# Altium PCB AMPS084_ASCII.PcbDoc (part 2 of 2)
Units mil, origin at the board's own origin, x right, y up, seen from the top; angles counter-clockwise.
Board outline 7000 x 5000 mil, 4 copper layers (Top Layer, Int 2 V-, Int 3 V+, Bottom Layer), stack 61.634 mil thick; 175 components, 69 nets, 389 pads, 136 vias.
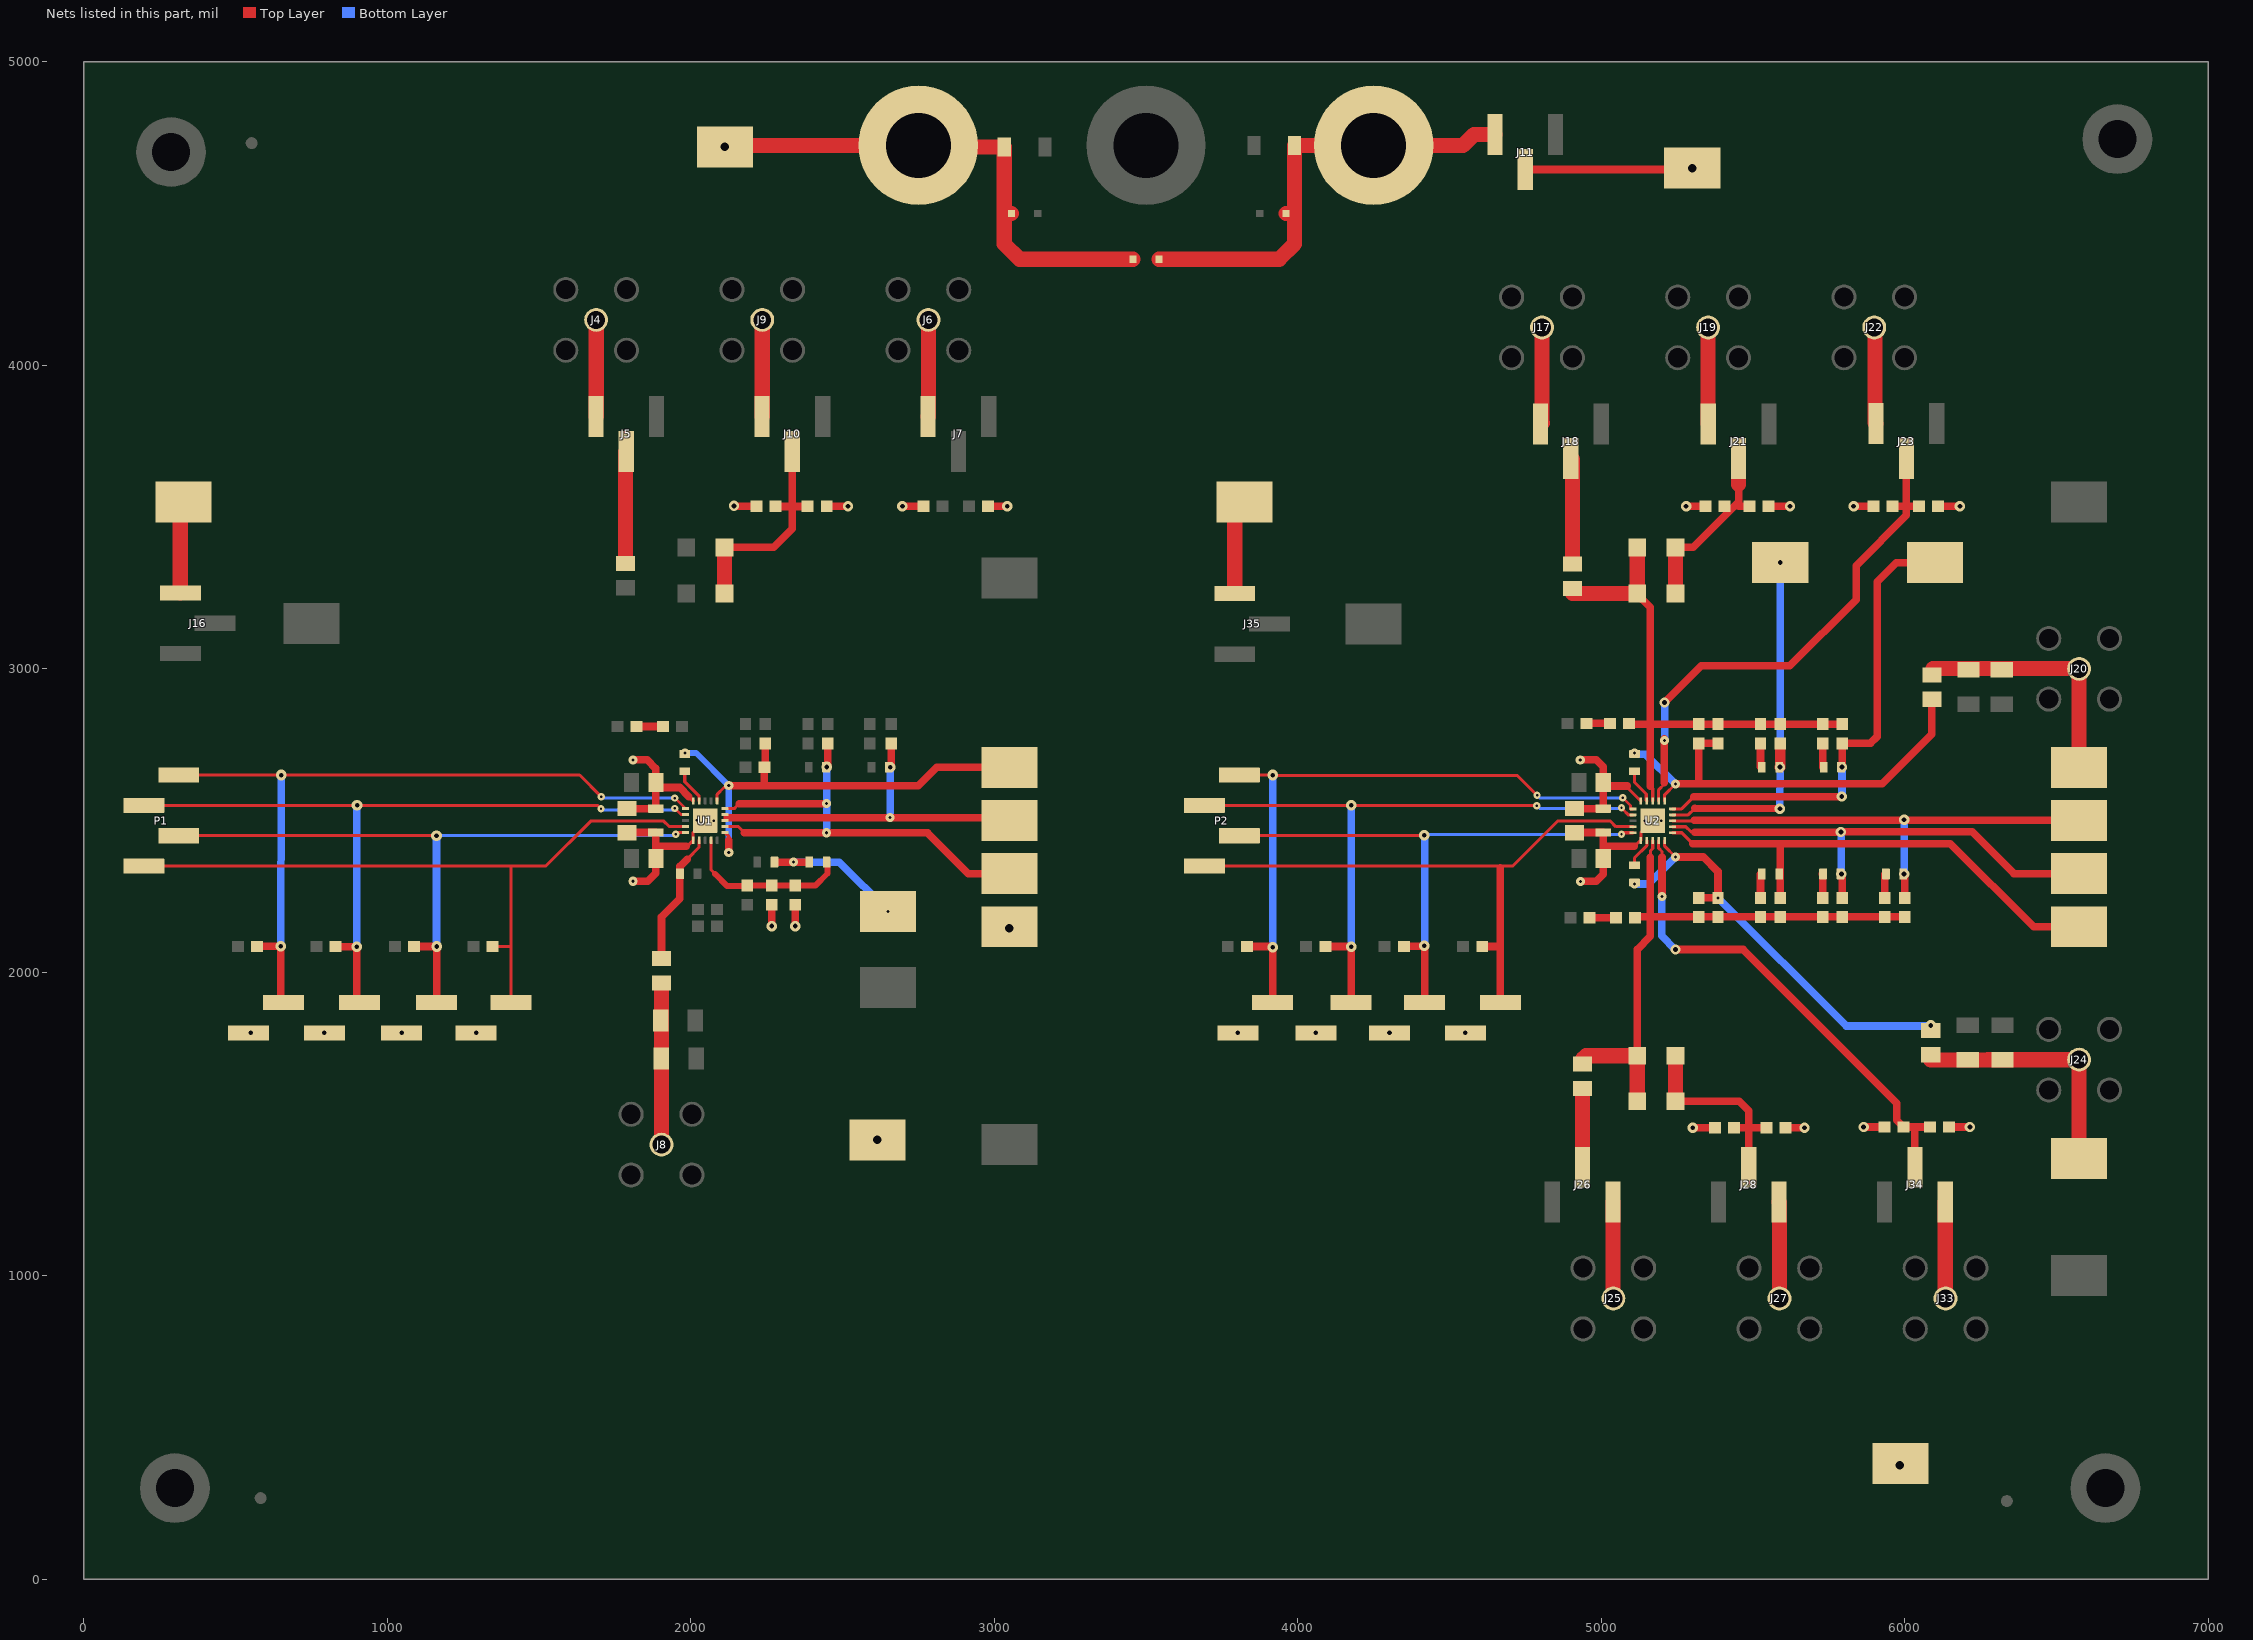
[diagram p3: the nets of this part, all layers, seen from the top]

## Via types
v1: diameter 34, hole 16, Top Layer to Bottom Layer, 61 vias
v2: diameter 35, hole 15, Top Layer to Bottom Layer, 28 vias
v3: diameter 30, hole 10, Top Layer to Bottom Layer, 22 vias
v4: diameter 24, hole 8, Top Layer to Bottom Layer, 16 vias
v5: diameter 50, hole 28, Top Layer to Bottom Layer, 9 vias

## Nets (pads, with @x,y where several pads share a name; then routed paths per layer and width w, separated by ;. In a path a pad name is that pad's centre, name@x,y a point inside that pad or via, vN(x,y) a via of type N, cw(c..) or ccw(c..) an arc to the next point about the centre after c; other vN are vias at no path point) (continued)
NetC6_1: C6.1 R5.1 | length 87
  Top Layer w25: C6.1@1821.5,2810 R5.1@1908.5,2810
NetC8_2: C8.2 J8.1 R11.2 R12.2 | length 515.9
  Top Layer w50: J8.1@1903.41,1432 R11.2@1903.41,1947.91
NetC12_1: C12.1 R28.1 | length 78.7
  Top Layer w25: C12.1@5730,2754.5 5730,2676.5 R28.1@5730.5,2676
NetC12_2: C12.2 C13.2 C15.2 D6.1 D7.2 R29.2 R30.1 R32.2 R33.1 R37.1 U2.18 | length 1774.3
  Top Layer w10: 5161.14,2613.79 5170,2604.93 U2.18@5170,2564.17
  Top Layer w25: R32.2@5091.5,2820 5093.5,2818 5161.14,2818 ; D6.1@5116.33,3247.96 5161.14,3203.15 5161.14,2818 ; 5161.14,2613.79 5161.14,2818 ; R30.1@5795,2817.5 R33.1@5590,2817.5 R37.1@5385,2817.5 5161.65,2817.5 5161.14,2818
  Top Layer w50: R29.2@4905.79,3247.96 5116.33,3247.96 5119.01,3250.64 D7.2@5119.01,3400
NetC13_1: C13.1 R31.1 | length 79.1
  Top Layer w25: C13.1@5525,2754.5 5525,2677.5 R31.1@5526.5,2676
NetC14_1: C14.1 R32.1 | length 77
  Top Layer w25: C14.1@4951.5,2820 R32.1@5028.5,2820
NetC16_2: C16.2 J20.1 R36.2 R38.2 TP19.1 | length 809.8
  Top Layer w50: R36.2@6093,3000.09 6093.91,3001 6576,3001 J20.1@6575,3000 TP19.1@6575,2675
NetC18_2: C18.2 J24.1 R42.2 R43.2 TP20.1 | length 811.4
  Top Layer w50: R42.2@6086,1710.98 R43.2@6208.03,1710.98 6273.34,1710.98 6274.36,1712 J24.1@6572,1712 ; TP20.1@6575,1387 J24.1@6575,1712
NetC22_2: C22.2 C24.2 C25.2 C26.2 D8.1 D9.2 R45.2 R48.2 R49.1 R52.1 R59.1 R61.1 U2.8 | length 1954.2
  Top Layer w10: 5161.91,2379.25 5162.1,2379.44 5162.1,2399.81 5170,2407.71 U2.8@5170,2434.25
  Top Layer w25: R48.2@5111.5,2180 5114,2182.5 5161.91,2182.5 ; D8.1@5118.73,1725 5118.73,2075 5161.91,2118.18 5161.91,2182.5 ; 5161.91,2379.25 5161.91,2182.5 ; R61.1@6000,2182.5 C25.2@5730,2182.5 C24.2@5525,2182.5 C22.2@5322,2182.5 5161.91,2182.5
  Top Layer w50: R45.2@4938.96,1714.28 4949.67,1725 D8.1@5118.73,1725 ; D9.2@5119.01,1575 D8.1@5119.01,1725
NetC23_1: C23.1 R48.1 | length 87
  Top Layer w25: C23.1@4961.5,2180 R48.1@5048.5,2180
NetC24_1: C24.1 R51.1 | length 79.1
  Top Layer w25: C24.1@5525,2245.5 5525,2322.5 R51.1@5526.5,2324
NetC25_1: C25.1 R58.1 | length 79.1
  Top Layer w25: R58.1@5728.5,2324 5730,2322.5 C25.1@5730,2245.5
NetC26_1: C26.1 R60.1 | length 78.7
  Top Layer w25: C26.1@5935,2245.5 5935,2323.5 R60.1@5935.5,2324
NetD4_2: D4.2 D5.1 J10.2 R15.1 R18.2 | length 762.9
  Top Layer w25: D5.1@2110.99,3400 2273,3400 2334.5,3461.5 2334.5,3535 ; R18.2@2278.99,3536 2279.99,3535 2334.5,3535 ; J10.2@2334.5,3716.5 2334.5,3535 ; R15.1@2385,3536 2384,3535 2334.5,3535
  Top Layer w50: D4.2@2110.79,3248.03 2110.99,3248.24 D5.1@2110.99,3400
NetD6_2: D6.2 D7.1 J21.2 R35.1 R39.2 | length 614.1
  Top Layer w25: D7.1@5244.99,3400 5302.93,3400 5452.93,3550 ; 5452.93,3607.94 5452.93,3550 ; R35.1@5488.5,3536 5452.93,3536 5452.93,3550
  Top Layer w50: D6.2@5244.99,3248 D7.1@5244.99,3400 ; 5452.93,3607.94 J21.2@5452.93,3692.5
NetD8_2: D8.2 D9.1 J28.2 R46.1 R47.2 | length 703.9
  Top Layer w25: D9.1@5244.99,1575 5455.11,1575 5486.46,1543.65 5486.46,1480.14 ; R46.1@5437.99,1487.74 5478.85,1487.74 5486.46,1480.14 ; J28.2@5486.46,1357.5 5486.46,1480.14 ; R47.2@5544.96,1487.74 5494.06,1487.74 5486.46,1480.14
  Top Layer w50: D9.1@5244.99,1575 D8.2@5244.99,1725
NetJ4_1: J4.1 J5.1 | length 317.8
  Top Layer w50: J5.1@1687.28,3831.56 1688.07,3832.34 J4.1@1688.07,4149.06
NetJ5_2: J5.2 R8.1 | length 353.3
  Top Layer w50: R8.1@1785.08,3364.17 1785.08,3714.35 J5.2@1787.28,3716.56
NetJ6_1: J6.1 J7.1 | length 317.8
  Top Layer w50: J7.1@2782.32,3831.56 2783.07,3832.3 J6.1@2783.07,4149.06
NetJ9_1: J9.1 J10.1 | length 318.9
  Top Layer w50: J10.1@2234.5,3831.5 2235.5,3832.5 J9.1@2235.5,4150
NetJ16_3: J16.3 TP12.1 | length 304.2
  Top Layer w50: J16.3@317.5,3250 317.5,3539.74 TP12.1@327.76,3550
NetJ17_1: J17.1 J18.1 | length 322.3
  Top Layer w50: J18.1@4800,3807.5 4805,3812.5 J17.1@4805,4125 ; J18.1@4803.86,3807.78 J18.1@4805.79,3809.7
NetJ18_2: J18.2 R29.1 | length 334.2
  Top Layer w50: R29.1@4903.86,3364.07 4905.79,3362.14 4905.79,3690.85 J18.2@4903.86,3692.78
NetJ19_1: J19.1 J21.1 | length 317.7
  Top Layer w50: J19.1@5352.5,4125 5352.5,3807.93 J21.1@5352.93,3807.5
NetJ22_1: J22.1 J23.1 | length 318.7
  Top Layer w50: J22.1@5902.85,4125.28 5902.85,3810.78 J23.1@5905.86,3807.78
NetJ23_2: J23.2 R40.1 R44.2 U2.17 | length 1729.9
  Top Layer w10: U2.17@5189.69,2564.17 5189.69,2601.06 5208.94,2620.32
  Top Layer w25: 5208,2625 v3@5208,2768.74 ; v1(5208.94,2889.22) 5329.72,3010 5622,3010 5840,3228 5840,3340 6005.86,3505.86 6005.86,3530 ; R44.2@5960.5,3536 5999.86,3536 6005.86,3530 ; J23.2@6005.86,3692.78 6005.86,3542 ; R40.1@6047.5,3536 6011.86,3536 6005.86,3542 ; 6005.86,3530 6005.86,3542
  Bottom Layer w25: v3(5208.94,2764.06) v1(5208.94,2889.22)
NetJ25_1: J25.1 J26.1 | length 317.5
  Top Layer w50: J25.1@5038.96,925 J26.1@5038.96,1242.5
NetJ26_2: J26.2 R45.1 | length 242.6
  Top Layer w50: J26.2@4938.96,1357.5 R45.1@4938.96,1600.11
NetJ27_1: J27.1 J28.1 | length 317.9
  Top Layer w50: J28.1@5586.46,1242.5 5587.5,1241.46 J27.1@5587.5,925
NetJ33_1: J33.1 J34.1 | length 317.5
  Top Layer w50: J33.1@6133.96,925 J34.1@6133.96,1242.5
NetJ34_2: J34.2 R50.1 R57.2 U2.9 | length 1628.2
  Top Layer w10: U2.9@5189.69,2434.25 5189.69,2408.66 5200.51,2397.84 5200.51,2379.25
  Top Layer w25: v3@5200.51,2249.74 5200.51,2379.25 ; v1(5244.72,2075) 5467.56,2075 5973.56,1569 5973.56,1512.93 R57.2@5996.5,1490 6033.96,1490 ; J34.2@6033.96,1357.5 6033.96,1490 ; R50.1@6083.5,1490 6033.96,1490
  Bottom Layer w25: v3(5200,2249.23) 5200,2119.72 v1(5244.72,2075)
NetJ35_3: J35.3 TP24.1 | length 315.2
  Top Layer w50: J35.3@3792.5,3248.23 3792.5,3517.5 TP24.1@3825,3550
NetR1_2: R1.2 R2.2 TP1.1 U1.12 U1.15 | length 1642
  Top Layer w10: U1.12@2112.2,2480.32 2156.46,2480.32 2176.93,2459.84 ; U1.15@2112.2,2539.37 2145,2539.37 2145,2541.1 2158.9,2555 ; TP1.1@3000,2325 TP1.1@3050,2325
  Top Layer w25: 2158.9,2555 2446.63,2555 v3(2447.74,2556.1) ; 2176.93,2459.84 v3(2447.74,2459.84) 2779.92,2459.84 2914.76,2325 TP1.1@3000,2325 ; R1.2@2448.5,2676 2451,2678.5 R2.2@2451,2754.5
  Bottom Layer w25: v3(2447.74,2459.84) v3(2447.74,2556.1) 2447.74,2675.82 v2(2448.38,2676.47)
NetR3_2: R3.2 R4.2 TP3.1 U1.13 U1.14 | length 1242.9
  Top Layer w10: U1.13@2112.2,2500 2112.2,2509.84 ; U1.14@2112.2,2519.69 2112.2,2509.84 ; 2155,2509.84 2112.2,2509.84
  Top Layer w25: 2120,2509.84 3040.16,2509.84 TP3.1@3050,2500 ; R3.2@2655.5,2676 2660,2680.5 R4.2@2660,2754.5
  Bottom Layer w25: v3(2657,2510) v2(2657,2676)
NetR9_1: R9.1 U1.19 | length 114.2
  Top Layer w10: R9.1@1980,2659.5 1980,2627.73 2027.56,2580.18 U1.19@2027.56,2564.96
NetR11_1: R11.1 R13.2 U1.7 | length 424.4
  Top Layer w10: 1987.83,2372.83 2027.56,2412.56 U1.7@2027.56,2435.04
  Top Layer w25: R11.1@1903.41,2062.09 1903.41,2182.27 1963.5,2242.37 1963.5,2285 1963.5,2348.5 1987.83,2372.83
NetR19_2: R19.2 R20.1 TP7.1 | length 489.9
  Top Layer w25: R19.2@2278.56,2363.26 v3(2338.03,2363.26) R20.1@2387.5,2363.26
  Bottom Layer w25: v3(2338.03,2363.26) 2489.03,2363.26 2650,2202.29 v3(2650,2200)
NetR20_2: R20.2 R21.2 R22.2 R23.2 U1.9 | length 557.8
  Top Layer w10: U1.9@2066.93,2435.04 2066.93,2336.73 2079.66,2324
  Top Layer w20: 2079.66,2324 2118.66,2285 2185.73,2285 R21.2@2186.33,2285.6 R22.2@2266.83,2285.6 R23.2@2344,2285.6 2410.52,2285.6 2450.5,2325.57 R20.2@2450.5,2363.26
NetR28_2: R28.2 R30.2 TP13.1 U2.15 | length 1601.2
  Top Layer w10: U2.15@5234.96,2538.58 5265.43,2538.58 5304.85,2578
  Top Layer w25: 5304.85,2578 5791.5,2578 v1(5793,2579.5) ; v1(5793.5,2676) 5795,2677.5 R30.2@5795,2754.5 5887.5,2754.5 5910,2777 5910,3287 5973,3350 TP13.1@6100,3350
  Bottom Layer w25: v1(5793,2579.5) 5793.5,2580 v1(5793.5,2676)
NetR31_2: R31.2 R33.2 TP16.1 U2.14 | length 1243
  Top Layer w10: U2.14@5234.96,2518.9 5286.9,2518.9 5308,2540
  Top Layer w25: 5308,2540 v1(5589,2539)
  Top Layer w35: v1(5589.5,2676) 5590,2676.5 R33.2@5590,2754.5
  Bottom Layer w25: v1(5589,2539) v1(5589.5,2676) v1@5589.5,3340.5
  other v1: 5590,3350
NetR34_1: R34.1 U2.19 | length 111.9
  Top Layer w10: R34.1@5110,2659.35 5110,2625.88 5148.5,2587.38 5148.5,2565.98 U2.19@5150.31,2564.17
NetR41_1: R41.1 U2.7 | length 95.4
  Top Layer w10: R41.1@5110,2355.52 5110,2377 5150.31,2417.31 U2.7@5150.31,2434.25
NetR51_2: R51.2 R52.2 TP22.1 U2.11 | length 1647.3
  Top Layer w10: U2.11@5234.96,2459.84 5265.96,2459.84 5301.8,2424
  Top Layer w25: 5301.8,2424 5589,2424 ; R52.2@5590,2245.5 5590,2323.5 5589.5,2324 5589.5,2423.5 5589,2424 ; TP22.1@6575,2150 6425,2150 6151,2424 5589,2424
NetR58_2: R58.2 R59.2 TP23.1 U2.12 | length 1625.2
  Top Layer w10: U2.12@5234.96,2479.53 5278.99,2479.53 5296.52,2462 5308,2462
  Top Layer w25: 5308,2462 v1(5790,2462) ; v1@5790,2463 6222.5,2463 6360.5,2325 TP23.1@6575,2325 ; v1(5791.5,2324) 5795,2320.5 R59.2@5795,2245.5
  Bottom Layer w25: v1@5790,2325.5 v1(5791.5,2324) 5791.5,2460.5 v1(5790,2462)
NetR60_2: R60.2 R61.2 TP25.1 U2.13 | length 1606.6
  Top Layer w10: U2.13@5234.96,2499.21 5301.79,2499.21 5307,2494
  Top Layer w25: 5307,2501 5935,2500.76 6574.24,2500.76 TP25.1@6575,2500 TP25.1@6575,2493.52 ; v1(5998.5,2324) 6000,2322.5 R61.2@6000,2245.5
  Bottom Layer w25: v1(5998.5,2324) v1(5998.5,2502.5)
OUTA_U1: R6.2 R7.2 R9.2 TP4.1 U1.11 U1.16 | length 1640.6
  Top Layer w10: U1.16@2086.61,2564.96 2086.61,2586.62 2109,2609 v3@2125,2609 ; U1.11@2112.2,2460.63 2125,2447.83 2125,2435
  Top Layer w25: v3(2125,2394.9) 2125,2435 ; v3(2125,2615) 2240,2615 ; R7.2@2245,2754.5 2245,2678.5 R6.2@2242.5,2676 2242.5,2617.5 2240,2615 ; TP4.1@3050,2675 2809.98,2675 2749.98,2615 2240,2615
  Bottom Layer w20: v3(1981,2723) 2017,2723 v3(2125,2615) v3(2125,2394.9)
OUTA_U2: C15.1 R34.2 R36.1 R37.2 U2.16 | length 1459.6
  Top Layer w10: U2.16@5209.37,2564.17 5209.37,2585.05 v3@5245,2620.68
  Top Layer w25: v3@5245,2620.68 5314,2620.68 ; R37.2@5385,2754.5 C15.1@5322,2754.5 5322,2628.68 5314,2620.68 ; R36.1@6090,2882.91 6090,2785 5925.68,2620.68 5314,2620.68
  Bottom Layer w25: v3(5110,2722) 5113,2719 5146,2719 v3(5245,2620)
OUTB_U2: C22.1 R41.2 R42.1 R49.2 U2.10 | length 1430.8
  Top Layer w10: U2.10@5209.37,2434.25 5209.37,2415.63 v3(5245,2380)
  Top Layer w25: v3(5245,2380) 5337,2380 5385,2332 R49.2@5385,2245.5 C22.1@5322,2245.5
  Bottom Layer w25: v3(5110,2291) 5156,2291 v3(5245,2380) ; v3@5384.5,2246 5807.5,1823 6087,1823 v1@6089,1825
  other v1: 6086,1825
  other v3: 5385,2245
SELA0_U1: J13.2 P1.2 R25.2 U1.2 | length 2526.7
  Top Layer w10: P1.2@197.5,2550 v2(900,2550) 1692.58,2550 v4(1704,2538.58) ; v4(1947,2540) 1967.31,2519.69 U1.2@1982.28,2519.69 ; v4@1950,2534.87 v4@1951.13,2534.87
  Top Layer w25: R25.2@828.96,2085 829.96,2084 v2(899,2084) 899,1908.48 J13.2@907.48,1900
  Bottom Layer w10: v4@1704,2535.58 1704.58,2535 1750,2535 1750.13,2534.87 v4@1950,2534.87
  Bottom Layer w25: v2(899,2084) 899,2549 v2(900,2550)
SELA0_U2: J30.2 P2.2 R54.2 U2.2 | length 2150.2
  Top Layer w10: P2.2@3692.5,2550 v2(4176,2550) 4177,2549 v4(4788,2549) ; v4@5072,2539 5072,2536.18 5089.28,2518.9 U2.2@5105.04,2518.9
  Top Layer w25: R54.2@4090.96,2085 4175,2085 v2(4176,2084) 4176,1901.24 J30.2@4174.96,1900.2
  Bottom Layer w10: v4(4788,2549) 4796.83,2540.17 v4@5059.9,2540.17
  Bottom Layer w25: v2(4176,2084) v2(4176,2550)
  other v4: 5067,2542
SELA1_U1: J12.2 P1.1 R24.2 U1.1 | length 2548.4
  Top Layer w10: P1.1@312.5,2650 v2(650,2650) 1633.84,2650 v4(1705,2578.84) ; v4(1947,2574) 1948.18,2574 1982.28,2539.89 U1.1@1982.28,2539.37
  Top Layer w25: R24.2@570.4,2085 571.4,2086 v2(649,2086) 649,1908.48 J12.2@657.48,1900
  Bottom Layer w10: v4(1705,2578.84) 1709.84,2574 v4(1947,2574)
  Bottom Layer w25: v2(649,2086) v2(650,2650)
SELA1_U2: J29.2 P2.1 R53.2 U2.1 | length 2188
  Top Layer w10: P2.1@3807.5,2650 v2(3918,2650) 3919.55,2648.45 4723.55,2648.45 v4(4788.75,2583.25) ; v4@5072,2571 5075.18,2571 5096.87,2549.3 5096.87,2538.58 U2.1@5105.04,2538.58
  Top Layer w25: R53.2@3832.4,2085 3916,2085 v2(3918,2083) 3918,1900.52 J29.2@3917.48,1900
  Bottom Layer w10: v4(4788.75,2583.25) 4798.13,2573.87 5069.13,2573.87 v4@5072,2571
  Bottom Layer w25: v2@3917,2084 v2(3918,2083) v2(3918,2650)
  other v4: 5071,2575
SELB0_U1: J15.2 P1.4 R27.2 U1.4 | length 2366.9
  Top Layer w10: P1.4@197.5,2350 1407.48,2350 ; R27.2@1346.06,2085 1402.48,2085 1407.48,2080 ; J15.2@1407.48,1900 1407.48,2080 ; U1.4@1982.28,2480.32 1928.94,2480.32 1911.22,2498.03 1670.08,2498.03 1522.05,2350 1407.48,2350 ; 1407.48,2080 1407.48,2350
SELB0_U2: J32.2 P2.4 R56.2 U2.4 | length 1994.4
  Top Layer w10: P2.4@3692.5,2350 4661.43,2350 ; 4667.48,2343.95 4661.43,2350 ; U2.4@5105.04,2479.53 5105.04,2479.87 5048.13,2479.87 5028.79,2499.21 4858,2499.21 4708.79,2350 4661.43,2350
  Top Layer w25: R56.2@4608.07,2085 4667.48,2085 ; J32.2@4667.48,1900.2 4667.48,2085 ; 4667.48,2343.95 4667.48,2085
SELB1_U1: J14.2 P1.3 R26.2 U1.5 | length 2300.6
  Top Layer w10: P1.3@312.5,2450 v2(1161.91,2450) ; v4@1948.74,2456.06 1953.31,2460.63 U1.5@1982.28,2460.63
  Top Layer w25: R26.2@1087.51,2085 v2(1163,2085) 1163,1901.09 J14.2@1161.91,1900
  Bottom Layer w10: v2(1161.91,2450) 1942.68,2450 v4@1948.74,2456.06
  Bottom Layer w20: v2@1161.91,2086.09 v2(1163,2085)
  Bottom Layer w25: v2@1161.91,2086.09 v2(1161.91,2450)
  other v4: 1950,2455
SELB1_U2: J31.2 P2.3 R55.2 U2.5 | length 1924.5
  Top Layer w10: P2.3@3807.5,2450 v2@4418,2450 ; v4@5072,2458 5073.84,2459.84 U2.5@5105.04,2459.84
  Top Layer w25: R55.2@4349.51,2085 4350.51,2086 4418,2086 4418,1900.72 J31.2@4417.48,1900.2
  Bottom Layer w10: v2@4418,2450 4422,2454 v4@5068,2454 ; v4@5072,2454 v4@5068,2454 ; v4@5072,2458 v4@5068,2454
  Bottom Layer w25: v2@4418,2086 v2@4418,2450
  other v2: 4417,2087 4417,2451
  other v4: 5067,2455
V+: C2.2 C7.2 C10.2 C11.1 C17.2 C19.2 C21.1 D1.1 D2.1 J1.1 J12.1 J13.1 J14.1 J15.1 J29.1 J30.1 J31.1 J32.1 R10.2 R15.2 R23.1 R35.2 R40.2 R46.2 R50.2 TP2.1 U1.20 U2.20 | length 3101.9
  Top Layer w8: 5086,2608.8 5086,2614 5086,2621
  Top Layer w10: 5086,2608.8 U2.20@5130.63,2564.17
  Top Layer w12: 1993.11,2578.74 2006.89,2564.96 U1.20@2007.87,2564.96
  Top Layer w25: C10.2@1790.37,2540 1791,2539.37 C11.1@1885,2539.37 C7.2@1885,2610 ; v3@1809,2700 1856.46,2700 1885,2671.46 C7.2@1885,2625 C7.2@1885,2610 ; 1993.11,2578.74 1962.85,2609 1886,2609 C7.2@1885,2610 ; v1(2344,2152) R23.1@2344,2222.61 ; R15.2@2447.99,3536 v1(2518,3536) v1@2519,3536 ; R10.2@2979.5,3536 v1(3042.74,3536) ; C19.2@4912,2540 4912.63,2539.37 C21.1@5007,2539.37 C17.2@5007,2625 5007,2677 4984,2700 v3@4932,2700 ; C17.2@5007.63,2614 5086,2614 ; v1(5301.8,1487.74) R46.2@5375,1487.74 ; R35.2@5551.5,3536 v1(5622,3536) ; R40.2@6110.5,3536 v1(6182,3536) ; R50.2@6146.5,1490 v1(6215,1490)
  Top Layer w50: v5(2112.2,4720) 2117.2,4725 J1.1@2750,4725 ; J1.1@2750,4720 3008.07,4720 ; C2.2@3033.07,4720 3033.07,4500 ; D1.1@3056.69,4500 3033.07,4500 ; D2.1@3456.69,4350 3083.07,4350 3033.07,4400 3033.07,4500
  other v2: 550,1800 792.52,1800 1046.95,1800 1292.52,1800 3802.52,1800 4060,1800 4302.52,1800.2 4552.52,1800.2
  other v3: 1810,2700 4931.08,2700
V-: C3.1 D2.2 D3.2 J3.1 J11.1 | length 1495
  Top Layer w50: D2.2@3543.31,4350 3939.19,4350 3989.19,4400 3989.19,4500 ; D3.2@3961.31,4500 3989.19,4500 ; J11.1@4650,4760.4 4580.4,4760.4 4545,4725 J3.1@4250,4725 C3.1@3989.19,4725 3989.19,4500
V-_Select: C9.1 C10.1 C11.2 C19.1 C20.1 C21.2 J11.2 R14.1 R18.1 R22.1 R39.1 R44.1 R47.1 R57.1 TP8.1 TP9.1 TP14.1 TP15.1 U1.6 U1.21 U2.6 U2.21 | length 2083.5
  Top Layer w10: 1984.09,2415 1987.83,2415 U1.6@2007.87,2435.04 2007.87,2460.63 U1.21@2047.24,2500 ; 5109.11,2415 5128.36,2434.25 U2.6@5130.63,2434.25 5130.63,2459.84 U2.21@5170,2499.21
  Top Layer w25: C10.1@1790.37,2460 1791,2460.63 C11.2@1885,2460.63 1885,2415 ; v3(1810,2300) 1858.29,2300 1885,2326.71 C9.1@1885,2375 1885,2415 ; 1984.09,2415 1885,2415 ; v1(2142,3537) 2143,3536 R18.1@2216,3536 ; v1(2266.83,2152) R22.1@2266.83,2222.61 ; v1(2697.07,3536) R14.1@2766.5,3536 ; J11.2@4750,4645.4 5295.4,4645.4 TP9.1@5300,4650 ; C19.1@4912,2460 4912.63,2460.63 C21.2@5007,2460.63 5007,2415 ; v3@4932,2300 4984,2300 5007,2323 C20.1@5007,2375 5007,2415 ; 5109.11,2415 5007,2415 ; v1(5280,3536) R39.1@5343.5,3536 ; R47.1@5607.95,1487.74 v1(5670,1487.74) ; v1(5832,3536) R44.1@5897.5,3536 ; v1(5865,1490) R57.1@5933.5,1490
  other v3: 4932.08,2299
  other v4: 5197.67,2499.21 2075,2500 5143,2500 2020,2500.69
  other v5: 5984,375 2615,1448.3 3050,2145 5300.85,4650
pads on no net: FID1.1 FID2.1 FID3.1 H1.1 H2.1 H3.1 H4.1

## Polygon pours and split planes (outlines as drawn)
V+ on Int 3 V+ "INT_3_V+_V+_P004" (solid, remove dead copper, pour order 4): 50,4950 6950,4950 6950,50 50,50
GND on Bottom Layer "BOTTOM_LAYER_GND_P006" (solid, remove dead copper, pour order 6): 50,4950 6950,4950 6950,50 50,50
V-_Select on Int 2 V- "INT_2_V-_V-_SELECT_P008" (solid, remove dead copper, pour order 8): 50,4950 6950,4950 6950,50 50,50
GND on Top Layer "TOP_LAYER_GND_P010" (solid, remove dead copper, pour order 10): 50,4950 50,50 6950,50 6950,4950

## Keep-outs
Keep-Out Layer:
  text ".Layer_Name" at 577,-858.49 h60

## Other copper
Top Layer:
  text ".Layer_Name" at 577,-858.49 h60
Bottom Layer:
  text ".Layer_Name" at 577,-858.49 h60

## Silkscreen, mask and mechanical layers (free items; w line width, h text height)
Top Overlay:
  lines w10: 180,1100 640,1100 ; 520,860 520,1200 ; 864.01,1100 1324.01,1100 ; 1204.01,860 1204.01,1200 ; 3496.5,4286.62 3500,379.46 ; 3542.52,1085 4002.52,1085 ; 3882.52,845 3882.52,1185 ; 4226.53,1085 4686.53,1085 ; 4566.53,845 4566.53,1185
  text "GND" at 4920,4830 h72.83
  text "V-" at 4504,4654 h72.83
  text "V+" at 2465,4474 h100
  text "SA1" at 5572,3007 h72.83 r90
  text "SA2" at 5770,3007 h72.83 r90
  text "No SW" at 5414.25,3001 h72.83 r90
  text "No SW" at 2242.5,2997.09 h72.83 r90
  text "SA1/SB1" at 2675,2995 h72.83 r90
  text "SA2/SB2" at 2475,2990 h72.83 r90
  text "SB3" at 2330,2980 h72.83 r90
  text "Int" at 275,2920 h60
  text "Int" at 3745,2910 h60
  text "SELA1" at 437.76,2660 h60
  text "SELA1" at 3985,2645 h60
  text "SELA0" at 533.07,2530 h60
  text "SELA0" at 3880,2530 h60
  text "SELB1" at 539.21,2424 h60
  text "SELB1" at 3930,2410 h60
  text "SELB0" at 3930,2330 h60
  text "SELB0" at 445,2320 h60
  text "SB1" at 5989,1863 h72.83 r90
  text "SB2" at 5799,1861 h72.83 r90
  text "SB3" at 5580,1860 h72.83 r90
  text "No SW" at 5370,1790 h72.83 r90
  text "Digital Select Int" at 3905.57,1557.5 h100
  text "Digital Select Int" at 650,1550 h100
  text "Shunt - '1'" at 815,1460 h60
  text "Shunt - '1'" at 4055,1455 h60
  text "Open - '0'" at 815,1395 h60
  text "Open - '0'" at 4055,1390 h60
  text "SELA1" at 160.96,1130 h60
  text "SELA0" at 344.41,1130 h60
  text "SW" at 533.07,1130 h60
  text "SELB1" at 844.98,1130 h60
  text "SELB0" at 1028.43,1130 h60
  text "SW" at 1217.08,1130 h60
  text "SELA1" at 3523.48,1115 h60
  text "SELA0" at 3706.93,1115 h60
  text "SW" at 3895.59,1115 h60
  text "SELB1" at 4207.5,1115 h60
  text "SELB0" at 4390.95,1115 h60
  text "SW" at 4579.6,1115 h60
  text "0" at 234.95,1050.28 h60
  text "0" at 418.4,1050.28 h60
  text "A1" at 533.07,1050 h60
  text "0" at 918.96,1050.28 h60
  text "0" at 1102.41,1050.28 h60
  text "B1" at 1217.08,1050 h60
  text "0" at 3597.47,1035.28 h60
  text "0" at 3780.92,1035.28 h60
  text "A1" at 3895.59,1035 h60
  text "0" at 4281.48,1035.28 h60
  text "0" at 4464.93,1035.28 h60
  text "B1" at 4579.6,1035 h60
  text "0" at 234.95,990.47 h60
  text "1" at 422.95,990.19 h60
  text "A2" at 533.07,990.19 h60
  text "0" at 918.96,990.47 h60
  text "1" at 1106.96,990.19 h60
  text "B2" at 1217.08,990.19 h60
  text "0" at 3597.47,975.47 h60
  text "1" at 3785.47,975.19 h60
  text "A2" at 3895.59,975.19 h60
  text "0" at 4281.48,975.47 h60
  text "1" at 4469.48,975.19 h60
  text "B2" at 4579.6,975.19 h60
  text "1" at 239.5,930.94 h60
  text "0" at 420,931.22 h60
  text "OPEN" at 533.07,931.01 h60
  text "1" at 923.51,930.94 h60
  text "0" at 1104.01,931.22 h60
  text "B3" at 1217.08,931.01 h60
  text "1" at 3602.02,915.94 h60
  text "0" at 3782.52,916.22 h60
  text "OPEN" at 3895.59,916.01 h60
  text "1" at 4286.03,915.94 h60
  text "0" at 4466.53,916.22 h60
  text "B3" at 4579.6,916.01 h60
  text "Special Mode" at 533.07,875.36 h60
  text "OPEN" at 1217.08,875.36 h60
  text "1" at 240,871.13 h60
  text "1" at 422.95,871.13 h60
  text "1" at 924.01,871.13 h60
  text "1" at 1106.96,871.13 h60
  text "Special Mode" at 3895.59,860.36 h60
  text "OPEN" at 4579.6,860.36 h60
  text "1" at 3602.52,856.13 h60
  text "1" at 3785.47,856.13 h60
  text "1" at 4286.53,856.13 h60
  text "1" at 4469.48,856.13 h60
  text ".Layer_Name" at 577,-858.49 h60
Bottom Overlay:
  text ".Layer_Name" at 577,-858.49 h60
Top Paste:
  text ".Layer_Name" at 577,-858.49 h60
Bottom Paste:
  text ".Layer_Name" at 577,-858.49 h60
Top Solder:
  text ".Layer_Name" at 577,-858.49 h60
  text ".Layer_Name" at 577,-858.49 h60
Bottom Solder:
  text ".Layer_Name" at 577,-858.49 h60
Drill Guide:
  text ".Layer_Name" at 577,-858.49 h60
M1 Board Outline:
  lines w10: 0,5000 0,0 7000,0 7000,5000 ; 0,5005 7000,5005
  text ".Layer_Name" at 577,-858.49 h60
M2 Board Dimensions:
  rectangle: 0,-275 125,-150
  rectangle: 125,-400 500,-275
  lines w7: 0,-275 1000,-275 ; 125,-400 125,-150 ; 250,-400 250,-150 ; 500,-400 500,-150 ; 750,-400 750,-150 ; 0,-400 1000,-400 1000,-150 0,-150 0,-400
  text ".Layer_Name" at 577,-858.49 h60
M3 3D STEP Top:
  text ".Layer_Name" at 577,-858.49 h60
M4 3D STEP Bottom:
  text ".Layer_Name" at 577,-858.49 h60
M5 Assembly Top:
  lines w10: -292,-930.17 6308,-930.17 ; -292,-726.83 6310,-726.83 ; -292,-523.5 -292,-1133.5 3713,-1133.5 6310,-1133.5 6310,-523.5 -291.5,-523.5 -291.5,-1133.5 1284,-1133.5 ; 2173,-1133.5 2173,-523.5 ; 3440,-726.83 3440,-523.5 ; 4280,-726.83 4280,-523.5 ; 4902,-1140 4902,-937.17
  text "COMPONENTS MARKED 'DNP' SHOULD NOT BE POPULATED." at 1153.5,-318.5 h60
  text "ASSEMBLY VARIANT:" at 1153,-434 h60
  text ".VariantName" at 2189,-434 h60
  text "PCB VIEWED FROM TOP SIDE" at -228.5,-655.67 h60
  text "BOARD #:" at 2248,-655.67 h60
  text ".PRJ_Number" at 2793.5,-655.67 h60
  text "REV:" at 3638,-655.67 h60
  text ".PCB_Rev" at 3929.5,-655.67 h60
  text "SVN REV:" at 4476,-655.67 h60
  text ".VersionControl_RevNumber" at 4982,-655.67 h60
  text "TID #:" at 2248,-859 h60
  text ".TID" at 2793.5,-859 h60
  text "PLOT NAME =" at -228.5,-1064.34 h60
  text ".plot_File_Name" at 577,-1064.34 h60
  text "GENERATED    :" at 2250,-1064.34 h60
  text ".Print_Date" at 3119.5,-1064.34 h60
  text ".Print_Time" at 3848.5,-1064.34 h60
  text "TEXAS INSTRUMENTS" at 5113,-1064.34 h60
M6 Assembly Bottom:
  lines w10: -292.5,-727.33 6309.5,-727.33 ; -290.5,-930.67 6309.5,-930.67 ; 1115.5,-1140.5 1115.5,-937.67 ; 1737.5,-727.33 1737.5,-524 ; 2577.5,-727.33 2577.5,-524 ; 3844.5,-1134 3844.5,-524 ; 4733.5,-1134 6309,-1134 6309,-524 -292.5,-524 -292.5,-1134 2304.5,-1134 6309.5,-1134 6309.5,-524
  text "COMPONENTS MARKED 'DNP' SHOULD NOT BE POPULATED." at 6102,-318 h60
  text ".VariantName" at 5058,-434 h60
  text "ASSEMBLY VARIANT:" at 6097,-434 h60
  text ".VersionControl_RevNumber" at 1035.5,-656.17 h60
  text "SVN REV:" at 1541.5,-656.17 h60
  text ".PCB_Rev" at 2088,-656.17 h60
  text "REV:" at 2379.5,-656.17 h60
  text ".PRJ_Number" at 3224,-656.17 h60
  text "BOARD #:" at 3769.5,-656.17 h60
  text "PCB VIEWED FROM BOTTOM SIDE" at 6246,-656.17 h60
  text ".TID" at 3224,-859.5 h60
  text "TID #:" at 3769.5,-859.5 h60
  text "TEXAS INSTRUMENTS" at 904.5,-1064.84 h60
  text ".Print_Time" at 2169,-1064.84 h60
  text ".Print_Date" at 2898,-1064.84 h60
  text "GENERATED    :" at 3767.5,-1064.84 h60
  text ".plot_File_Name" at 5440.5,-1064.84 h60
  text "PLOT NAME =" at 6246,-1064.84 h60
M9 Title Sheet:
  lines w10: -491.5,1041.5 -291.5,1041.5 ; -491.5,3416.5 -291.5,3416.5 ; -491.5,5791.5 -291.5,5791.5 ; 2008.5,-1333.5 2008.5,-1133.5 ; 2008.5,7966.5 2008.5,8166.5 ; 4508.5,-1333.5 4508.5,-1133.5 ; 4508.5,7966.5 4508.5,8166.5 ; 6321,-1133.5 6321,-523.5 11303.5,-523.5 ; 7008.5,-1333.5 7008.5,-1133.5 ; 7008.5,7966.5 7008.5,8166.5 ; 9508.5,-1333.5 9508.5,-1133.5 ; 9508.5,7966.5 9508.5,8166.5 ; 11303.5,-1133.5 11303.5,-523.5 ; 11303.5,-823.5 14303.5,-823.5 ; 11303.5,-223.5 14303.5,-223.5 ; 11304.5,370.5 14304.5,370.5 ; 12008.5,-1333.5 12008.5,-1133.5 ; 12008.5,7966.5 12008.5,8166.5 ; 12808.5,-1123.5 12808.5,-523.5 ; 14303.5,-523.5 11303.5,-523.5 ; 14303.5,76.5 11303.5,76.5 ; 14308.5,66.5 14308.5,-1133.5 ; 14308.5,871 11304.5,871 11303.5,871 11303.5,370.5 11303.5,76.5 ; 14308.5,1041.5 14508.5,1041.5 ; 14308.5,3416.5 14508.5,3416.5 ; 14308.5,5791.5 14508.5,5791.5 ; 11303.5,-523.5 11303.5,76.5 ; 14308.5,-1133.5 14308.5,7966.5 -291.5,7966.5 -291.5,-1133.5 14308.5,-1133.5 ; -491.5,-1333.5 -491.5,8166.5 14508.5,8166.5 14508.5,-1333.5 -491.5,-1333.5
  text "1" at 739.84,8036.5 h70
  text "2" at 3235.5,8036.5 h70
  text "3" at 5724.84,8036.5 h70
  text "4" at 8231.51,8036.5 h70
  text "5" at 10730.5,8036.5 h70
  text "6" at 13235.5,8036.5 h70
  text "A" at -416.5,6893.5 h70
  text "A" at 14383.5,6893.5 h70
  text "B" at -416.5,4513.5 h70
  text "B" at 14383.5,4513.5 h70
  text "C" at -416.5,2138.5 h70
  text "C" at 14383.5,2138.5 h70
  text "PROJECT TITLE:" at 11343.5,277.5 h45
  text ".PRJ_Title" at 11393.5,144.17 h70
  text "DESIGNED FOR:" at 11343.5,-23.5 h45
  text ".PRJ_Customer" at 11393.5,-163.5 h70
  text "D" at -416.5,-231.5 h70
  text "D" at 14383.5,-231.5 h70
  text "FILE NAME:" at 11343.5,-323.5 h45
  text ".PCB_File_Name_No_Path" at 11393.5,-443.5 h70
  text "Texas Instruments (TI) and/or its licensors do not warrant the accuracy or completeness of this specification" at 6374,-605.34 h45
  text "ENGINEER:" at 11343.5,-613.5 h45
  text "LAYOUT BY:" at 12848.5,-613.5 h45
  text "or any information contained therein. TI and/or its licensors do not warrant that this design will meet" at 6329.01,-718 h45
  text ".PRJ_Engineer" at 11393.5,-768.49 h70
  text ".PCB_Layout" at 12899,-768.49 h70
  text "the specifications, will be suitable for your application or fit for any particular purpose, or will operate in" at 6329.01,-830.67 h45
  text ".Layer_Name" at 577,-858.49 h60
  text "ALTIUM DESIGNER VERSION:" at 12848.5,-923.5 h45
  text "an implementation. TI and/or its licensors do not warrant that the design is production worthy. You should" at 6329.01,-943.33 h45
  text "completely validate and test your design implementation to confirm the system functionality for your application." at 6374,-1056 h45
  text ".print_Scale" at 11393.5,-1056.83 h70
  text ".Application_BuildNumber" at 12899,-1056.83 h70
  text "1" at 739.84,-1263.5 h70
  text "2" at 3235.5,-1263.5 h70
  text "3" at 5724.84,-1263.5 h70
  text "4" at 8231.51,-1263.5 h70
  text "5" at 10730.5,-1263.5 h70
  text "6" at 13235.5,-1263.5 h70
M10 Fab Notes:
  drawing of 189 lines, arcs and shapes, not listed
  text "DESIGN INFORMATION" at 12382.02,6356.17 h60
  text "MIN. TRACK WIDTH:" at 11737.46,6224.05 h60
  text "8" at 12833.7,6224.05 h60
  text "MIL" at 12988.46,6224.05 h60
  text "MIN. CLEARANCE:" at 11737.46,6099.92 h60
  text "0.2" at 12773.7,6099.93 h60
  text "mm" at 12988.46,6099.92 h60
  text "MIN. VIA PAD SIZE:" at 11737.46,5975.8 h60
  text "24" at 12803.71,5975.8 h60
  text "MIL" at 12988.46,5975.8 h60
  text "0.05mm (2MIL)" at 12432.46,5845.9 h60
  text "MINIMUM ANNULAR RING" at 11408.23,5837.67 h60
  text "EXTERNAL" at 13140.46,5837.67 h60
  text "PER" at 11608.23,5727.55 h60
  text "IPC-D-275 CLASS 2 LEVEL C" at 11828.23,5727.54 h60
  text "MIL, HOLES" at 13316.46,5627.07 h60
  text "+/-" at 12924,5618.48 h60
  text "+/-" at 13778,5618.48 h60
  text "REGISTRATION TOLERANCES:" at 11408.23,5617.42 h60
  text "METAL" at 12608,5617.42 h60
  text "5" at 13184.2,5617.42 h60
  text "3" at 14017.2,5617.42 h60
  text "MIL" at 14133.46,5617.42 h60
  text "HOLE SIZE TOLERANCE (UNLESS OTHERWISE SPECIFIED):" at 11408.23,5519.1 h60
  text "+/-" at 13778,5516.23 h60
  text "3" at 14017.2,5515.17 h60
  text "MIL" at 14133.46,5515.17 h60
  text "MATERIAL:" at 11333.46,5377.52 h60
  text "FR-4 High Tg" at 12319.9,5249 h60
  text "X" at 12175.46,5241.01 h60
  text "FR-408" at 11754.46,5236.49 h60
  text "OTHER" at 13242.46,5236.49 h60
  text "62 MIL (1.6mm) +/-10%" at 12074.56,5093.46 h60
  text "X" at 11954.46,5091.01 h60
  text "THICKNESS:" at 11408.23,5085.24 h60
  text "OTHER" at 13359.46,5085.24 h60
  text "TOLERANCE:" at 11408.23,4946.92 h60
  text "X" at 12256.46,4946.92 h60
  text "ANSI IPC-6012 TYPE 3 CLASS 2" at 12434.48,4946.92 h60
  text "OTHER +/-" at 12434.46,4802.73 h60
  text "BOW & TWIST:" at 11408.23,4657.54 h60
  text "X" at 12256.46,4657.54 h60
  text "ANSI IPC-6012 TYPE 3 CLASS 2" at 12434.48,4657.54 h60
  text "OTHER +/-" at 12434.46,4510.85 h60
  text "DRILLING:" at 11333.46,4380.23 h60
  text "NC_DRILL FILES" at 13094.46,4275.04 h60
  text "REFERENCE:" at 11408.23,4271.1 h60
  text "X" at 12065.46,4271.01 h60
  text "AS SHOWN" at 12243.46,4271.1 h60
  text "X" at 12966.46,4271.1 h60
  text "OTHER" at 13392.46,4128.85 h60
  text "PTH COPPER THICKNESS:" at 11407.91,4125.32 h60
  text "X" at 12547.14,4125.32 h60
  text "20-30 um" at 12675.14,4125.32 h60
  text "BOARD FINISH:" at 11333.46,3977.73 h60
  text "SILKSCREEN:" at 11488.68,3867.6 h60
  text "X" at 12446.46,3867.6 h60
  text "TOP" at 12563.46,3867.6 h60
  text "X" at 12956.46,3867.6 h60
  text "BOTTOM" at 13074.46,3867.6 h60
  text "SILKSCREEN COLOR:" at 11488.68,3712.41 h60
  text "X" at 12445.46,3712.41 h60
  text "WHITE" at 12563.46,3712.41 h60
  text "OTHER" at 13074.46,3712.41 h60
  text "X" at 12576.46,3568.96 h60
  text "GREEN" at 12694.46,3568.96 h60
  text "OTHER" at 13312.46,3568.96 h60
  text "SOLDER RESIST COLOR:" at 11488.68,3562.1 h60
  text "X" at 12576.46,3414.71 h60
  text "MATTE" at 12694.46,3414.71 h60
  text "SEMI-GLOSS" at 13312,3414.07 h60
  text "IMMERSION GOLD (ENIG)" at 12394.46,3241.94 h60
  text "ENEPIG" at 13732,3234.72 h60
  text "SURFACE FINISH:" at 11333.46,3233.72 h60
  text "X" at 12216.46,3233.72 h60
  text "IMM. TIN/SILVER OR EQUIV" at 11663,3096.4 h60
  text "OTHER" at 13094.46,3092.47 h60
  text "ARRAY/PANEL:" at 11333.46,2937.09 h60
  text "CUT AND TRIM PER M1 BOARD OUTLINE" at 12394.46,2928.87 h60
  text "N.C. ROUTE" at 12394.46,2792.9 h60
  text "X" at 13082.46,2792.9 h60
  text "V. SCORE" at 13260.46,2792.9 h60
  text "CERTIFICATION:" at 11333.46,2663.77 h60
  text "MATERIALS AND WORKMANSHIP FOR ALL PCBS" at 12058.46,2663.77 h60
  text "TO MEET OR EXCEED THE REQUIREMENTS OF:" at 12058.46,2569.71 h60
  text "X" at 11695.97,2441.08 h60
  text "ANSI IPC-A-600F CLASS ->" at 11823.96,2441.08 h60
  text "X" at 13471.97,2441.08 h60
  text "2" at 13581.96,2441.08 h60
  text "1" at 13266.96,2439.58 h60
  text "3" at 13935.96,2439.58 h60
  text "X" at 12507.97,2293.39 h60
  text "RoHS" at 12635.96,2293.39 h60
  text "OTHER" at 13280.36,2293.39 h60
  text "PER ORDER" at 13677.42,2293.39 h60
  text "ALL BOARDS MUST MEET OR EXCEED UL94-V0 REQUIREMENTS." at 11361,2139.57 h60
  text "PCB MUST BEAR THE UL94V-0 UL REGISTERED MATERIAL ID NUMBER" at 11361,2023.5 h60
  text "ADDITIONAL REQUIREMENTS:" at 11333.46,1854.08 h60
  text "MICROSECTION:" at 11408.23,1746.95 h60
  text "YES" at 12313.96,1746.95 h60
  text "REQUIRED" at 13175.46,1602.62 h60
  text "BARE BOARD ELEC. TEST:" at 11408.23,1599.76 h60
  text "NONE" at 12713.96,1599.76 h60
  text "X" at 13057.46,1599.76 h60
  text "PER ORDER" at 13767.46,1599.76 h60
  text "XX MIL VIAS REQUIRE NON-CONDUCTIVE FILL AND PLANARIZE" at 11576.38,1394.82 h59
  text "XX MIL VIAS REQUIRE CONDUCTIVE FILL AND PLANARIZE" at 11584.38,1290.84 h60
  text "OUTER XX MIL TRACES REQUIRE 50 OHM SINGLE-ENDED IMPEDANCE" at 11583.39,1127.46 h58
  text "LAYER 2 & 3 (INNER LAYERS) XX MIL WIDE, XX MIL SPACE / TRACES REQUIRE 100 OHM DIFFERENTIAL IMPEDANCE" at 11575.39,891.74 h60
  text ".Layer_Name" at 577,-858.49 h60
M11 Gerber Information:
  lines w10: -292,-930.17 6308,-930.17 ; -292,-726.83 6310,-726.83 ; -292,-523.5 -292,-1133.5 3713,-1133.5 6310,-1133.5 6310,-523.5 -291.5,-523.5 -291.5,-1133.5 1284,-1133.5 ; 2173,-1133.5 2173,-523.5 ; 3440,-726.83 3440,-523.5 ; 4280,-726.83 4280,-523.5 ; 4902,-1140 4902,-937.17
  text "ALL ARTWORK VIEWED FROM TOP SIDE" at -228.5,-655.67 h60
  text "BOARD #:" at 2248,-655.67 h60
  text ".PRJ_Number" at 2793.5,-655.67 h60
  text "REV:" at 3638,-655.67 h60
  text ".PCB_Rev" at 3929.5,-655.67 h60
  text "SVN REV:" at 4476,-655.67 h60
  text ".VersionControl_RevNumber" at 4982,-655.67 h60
  text "LAYER NAME =" at -228.5,-858.49 h60
  text "TID #:" at 2248,-859 h60
  text ".TID" at 2793.5,-859 h60
  text "PLOT NAME =" at -228.5,-1064.34 h60
  text ".plot_File_Name" at 577,-1064.34 h60
  text "GENERATED    :" at 2250,-1064.34 h60
  text ".Print_Date" at 3119.5,-1064.34 h60
  text ".Print_Time" at 3848.5,-1064.34 h60
  text "TEXAS INSTRUMENTS" at 5113,-1064.34 h60
M12 Stackup:
  drawing of 295 lines, arcs and shapes, not listed
  text "Layer" at 6425.09,7122.5 h60
  text "Name" at 6835,7122.5 h60
  text "Material" at 7764.74,7122.5 h60
  text "Thickness" at 8624.51,7122.5 h60
  text "Constant" at 9274.35,7122.5 h60
  text "Board Layer Stack" at 9844.21,7122.5 h60
  text "1" at 6425.09,7002.5 h60
  text "Top Overlay" at 6835,7002.5 h60
  text "2" at 6425.09,6882.5 h60
  text "Top Solder" at 6835,6882.5 h60
  text "Solder Resist" at 7764.74,6882.5 h60
  text "0.40mil" at 8624.51,6882.5 h60
  text "3.5" at 9274.35,6882.5 h60
  text "3" at 6425.09,6762.5 h60
  text "Top Layer" at 6835,6762.5 h60
  text "Copper" at 7764.74,6762.5 h60
  text "1.40mil" at 8624.51,6762.5 h60
  text "4" at 6425.09,6642.5 h60
  text "Dielectric 2" at 6835,6642.5 h60
  text "10.00mil" at 8624.51,6642.5 h60
  text "4.2" at 9274.35,6642.5 h60
  text "5" at 6425.09,6522.5 h60
  text "Int 2 V-" at 6835,6522.5 h60
  text "Copper" at 7764.74,6522.5 h60
  text "1.42mil" at 8624.51,6522.5 h60
  text "6" at 6425.09,6402.5 h60
  text "Dielectric1" at 6835,6402.5 h60
  text "FR-4" at 7764.74,6402.5 h60
  text "36.00mil" at 8624.51,6402.5 h60
  text "4.8" at 9274.35,6402.5 h60
  text "7" at 6425.09,6282.5 h60
  text "Int 3 V+" at 6835,6282.5 h60
  text "Copper" at 7764.74,6282.5 h60
  text "1.42mil" at 8624.51,6282.5 h60
  text "8" at 6425.09,6162.5 h60
  text "Dielectric 3" at 6835,6162.5 h60
  text "10.00mil" at 8624.51,6162.5 h60
  text "4.2" at 9274.35,6162.5 h60
  text "9" at 6425.09,6042.5 h60
  text "Bottom Layer" at 6835,6042.5 h60
  text "Copper" at 7764.74,6042.5 h60
  text "1.40mil" at 8624.51,6042.5 h60
  text "10" at 6425.09,5922.5 h60
  text "Bottom Solder" at 6835,5922.5 h60
  text "Solder Resist" at 7764.74,5922.5 h60
  text "0.40mil" at 8624.51,5922.5 h60
  text "3.5" at 9274.35,5922.5 h60
  text "11" at 6425.09,5802.5 h60
  text "Bottom Overlay" at 6835,5802.5 h60
  text ".Layer_Name" at 577,-858.49 h60
M13 Component Bodies Top:
  text ".Layer_Name" at 577,-858.49 h60
M14 Component Bodies Bottom:
  text ".Layer_Name" at 577,-858.49 h60
M15 Courtyards Top:
  text ".Layer_Name" at 577,-858.49 h60
M16 Courtyards Bottom:
  text ".Layer_Name" at 577,-858.49 h60
Drill Drawing:
  circle w10: c7410.96,5717.8 r27.63
  circle w10: c7410.96,5344.84 r16.58
  circle w10: c7410.96,5344.84 r27.63
  lines w10: 7383.33,4958.07 7397.15,4958.07 7410.96,4944.25 7424.77,4958.07 7438.59,4958.07 7424.77,4971.88 7438.59,4985.69 7424.77,4985.69 7410.96,4999.51 7397.15,4985.69 7383.33,4985.69 7397.15,4971.88 7383.33,4958.07 ; 7383.33,5068.57 7410.96,5082.39 7438.59,5068.57 7424.77,5096.2 7438.59,5123.83 7410.96,5110.01 7383.33,5123.83 7397.15,5096.2 7383.33,5068.57 ; 7383.33,5192.89 7438.59,5192.89 7438.59,5248.15 7383.33,5248.15 7383.33,5192.89 ; 7383.33,5469.16 7410.96,5441.53 7438.59,5469.16 7410.96,5496.79 7383.33,5469.16 ; 7383.33,5565.85 7438.59,5565.85 7438.59,5621.11 7383.33,5621.11 7383.33,5565.85 ; 7383.33,5814.49 7383.33,5828.31 7397.15,5842.12 7383.33,5855.93 7383.33,5869.75 7397.15,5869.75 7410.96,5855.93 7424.77,5869.75 7438.59,5869.75 7438.59,5855.93 7424.77,5842.12 7438.59,5828.31 7438.59,5814.49 7424.77,5814.49 7410.96,5828.31 7397.15,5814.49 7383.33,5814.49 ; 7383.33,5994.07 7438.59,5994.07 7410.96,5938.81 7383.33,5994.07 ; 7394.39,5203.94 7427.54,5203.94 7427.54,5237.1 7394.39,5237.1 7394.39,5203.94
  lines w12: 7333.24,4906.96 10564.73,4906.96 ; 7333.24,6025.84 10564.73,6025.84 ; 7671.11,4782.64 7671.11,6150.16 ; 8003.11,4782.64 8003.11,6150.16 ; 8639.67,4782.64 8639.67,6150.16 ; 8898.81,4782.64 8898.81,6150.16 ; 9273.97,4782.64 9273.97,6150.16 ; 9998.3,4782.64 9998.3,6150.16 ; 7333.24,4782.64 10564.73,4782.64 10564.73,6150.16 7333.24,6150.16 7333.24,4782.64
  text "Symbol" at 7407.84,6063.13 h72
  text "Quantity" at 7708.4,6063.13 h72
  text "Finished Hole Size" at 8040.4,6063.13 h72
  text "Plated" at 8676.97,6063.13 h72
  text "Hole Type" at 8936.11,6063.13 h72
  text "Drill Layer Pair" at 9311.26,6063.13 h72
  text "Hole Tolerance" at 10035.59,6063.13 h72
  text "16" at 7708.4,5938.81 h60
  text "8.00mil (0.203mm)" at 8040.4,5938.81 h60
  text "PTH" at 8676.97,5938.81 h60
  text "Round" at 8936.11,5938.81 h60
  text "Top Layer - Bottom Layer" at 9311.26,5938.81 h60
  text "22" at 7708.4,5814.49 h60
  text "10.00mil (0.254mm)" at 8040.4,5814.49 h60
  text "PTH" at 8676.97,5814.49 h60
  text "Round" at 8936.11,5814.49 h60
  text "Top Layer - Bottom Layer" at 9311.26,5814.49 h60
  text "28" at 7708.4,5690.17 h60
  text "15.00mil (0.381mm)" at 8040.4,5690.17 h60
  text "PTH" at 8676.97,5690.17 h60
  text "Round" at 8936.11,5690.17 h60
  text "Top Layer - Bottom Layer" at 9311.26,5690.17 h60
  text "61" at 7708.4,5565.85 h60
  text "16.00mil (0.406mm)" at 8040.4,5565.85 h60
  text "PTH" at 8676.97,5565.85 h60
  text "Round" at 8936.11,5565.85 h60
  text "Top Layer - Bottom Layer" at 9311.26,5565.85 h60
  text "9" at 7708.4,5441.53 h60
  text "28.00mil (0.711mm)" at 8040.4,5441.53 h60
  text "PTH" at 8676.97,5441.53 h60
  text "Round" at 8936.11,5441.53 h60
  text "Top Layer - Bottom Layer" at 9311.26,5441.53 h60
  text "12" at 7708.4,5317.21 h60
  text "59.06mil (1.500mm)" at 8040.4,5317.21 h60
  text "PTH" at 8676.97,5317.21 h60
  text "Round" at 8936.11,5317.21 h60
  text "Top Layer - Bottom Layer" at 9311.26,5317.21 h60
  text "48" at 7708.4,5192.89 h60
  text "62.99mil (1.600mm)" at 8040.4,5192.89 h60
  text "PTH" at 8676.97,5192.89 h60
  text "Round" at 8936.11,5192.89 h60
  text "Top Layer - Bottom Layer" at 9311.26,5192.89 h60
  text "4" at 7708.4,5068.57 h60
  text "125.00mil (3.175mm)" at 8040.4,5068.57 h60
  text "PTH" at 8676.97,5068.57 h60
  text "Round" at 8936.11,5068.57 h60
  text "Top Layer - Bottom Layer" at 9311.26,5068.57 h60
  text "3" at 7708.4,4944.25 h60
  text "214.57mil (5.450mm)" at 8040.4,4944.25 h60
  text "PTH" at 8676.97,4944.25 h60
  text "Round" at 8936.11,4944.25 h60
  text "Top Layer - Bottom Layer" at 9311.26,4944.25 h60
  text "203 Total" at 7708.4,4819.93 h60
  text ".Layer_Name" at 577,-858.49 h60
M17 Embedded Cavity:
  text ".Layer_Name" at 577,-858.49 h60
M18 Embedded Assembly:
  text ".Layer_Name" at 577,-858.49 h60
M19 Embedded Keepout:
  text ".Layer_Name" at 577,-858.49 h60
